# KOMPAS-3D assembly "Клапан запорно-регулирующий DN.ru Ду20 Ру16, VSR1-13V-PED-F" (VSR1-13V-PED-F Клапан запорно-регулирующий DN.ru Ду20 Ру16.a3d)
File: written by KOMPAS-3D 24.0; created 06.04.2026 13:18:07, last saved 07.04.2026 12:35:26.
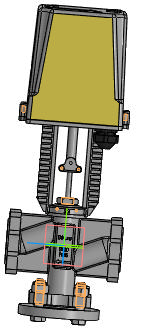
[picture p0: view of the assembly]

Document properties: Автор: R2D2; Полное имя файла: E:\Работа\Зайцев\Солянка\VSR1-13V-PED-F Клапан запорно-регулирующий DN.ru\DN20\исходные материалы\VSR1-13V-PED-F Клапан запорно-регулирующий DN.ru Ду20 Ру16.a3d

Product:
- Component [detail]: Фланец Ду15 Ру16  | qty 2  | pos. 1  | Масса: 0.613226; Автор: R2D2; source file: Фланец.m3d
- Component [detail]: Фланец Ду15 Ру16  | qty 1  | pos. 2  | Масса: 0.613226; Автор: R2D2; source file: Фланец.m3d
- Component [detail]: Корпус  | qty 1  | pos. 3  | Масса: 6.9; Автор: R2D2; source file: Корпус.m3d
- Component [detail]: Электропривод  | qty 1  | pos. 6  | Масса: 0.101125; Автор: R2D2; source file: Электропривод.m3d
- Component [standard]: Болт М12-6gx45 ГОСТ 7796-70  | qty 4  | Масса: 0.05148; Раздел спецификации: Стандартные изделия; Рассекать на разрезах: no; additional columns: М8x1-6gx12
- Component [standard]: Гайка М12-6H ГОСТ 5915-70  | qty 4  | Масса: 0.0184; Раздел спецификации: Стандартные изделия; Рассекать на разрезах: no; additional columns: М1,6-6H.12
- Part/product: Клапан запорно-регулирующий DN.ru Ду20 Ру16  | designation VSR1-13V-PED-F
    Масса: 6.9
    Раздел спецификации: Прочие изделия
    Примечание: D090-02887

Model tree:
1. Эскиз:1
2. Болтовое соединение
3. Массив по концентрической сетке:1  (with: Грань.Элемент вращения:1, Грань.Элемент выдавливания:1, Грань.Элемент выдавливания:2)  (4 pattern instances)
     Шаг 2 = 360; Ориентация = 2; Расстояние = 2; Расстояние = -30

Expressions: VSR1-13V-PED-F; -L/2
Referenced files in E:\Работа\Зайцев\Солянка\VSR1-13V-PED-F Клапан запорно-регулирующий DN.ru\DN20\исходные материалы\: Фланец.m3d, Корпус.m3d, Электропривод.m3d
Referenced files in C:\Program Files\ASCON\KOMPAS-3D v24\Libs\PolynomLib\DATA\vault\Methods\Kompas\3D\: PLib_Bolt_1_900.m3d, PLib_Nut_OST92_900.m3d
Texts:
  Крепежное изделие ГОСТ
  Программные изделия  и базы данных
  Edge1
  Edge2
  TKR3D
  Справочник стандартных изделий
  Фланец Ду15 Ру16 (1)
  Фланец Ду15 Ру16 (2)
  Фланец Ду15 Ру16 (3)
  Болт М12-6gx45 ГОСТ 7796-70 (1)
  hole1
  hole2
  Гайка М12-6H ГОСТ 5915-70 (1)
  bcut1
  hcut1
  cut1
  Гайка М12-6H ГОСТ 5915-70 (2)
  Болт М12-6gx45 ГОСТ 7796-70 (2)
  Гайка М12-6H ГОСТ 5915-70 (3)
  Болт М12-6gx45 ГОСТ 7796-70 (3)
  Гайка М12-6H ГОСТ 5915-70 (4)
  Болт М12-6gx45 ГОСТ 7796-70 (4)
  Плоскость XY.Начало координат
  Ось Z.Начало координат
  Плоскость ZY.Начало координат
  Плоскость ZX.Начало координат
  Ось Y.Начало координат
  Plane. Начало координат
